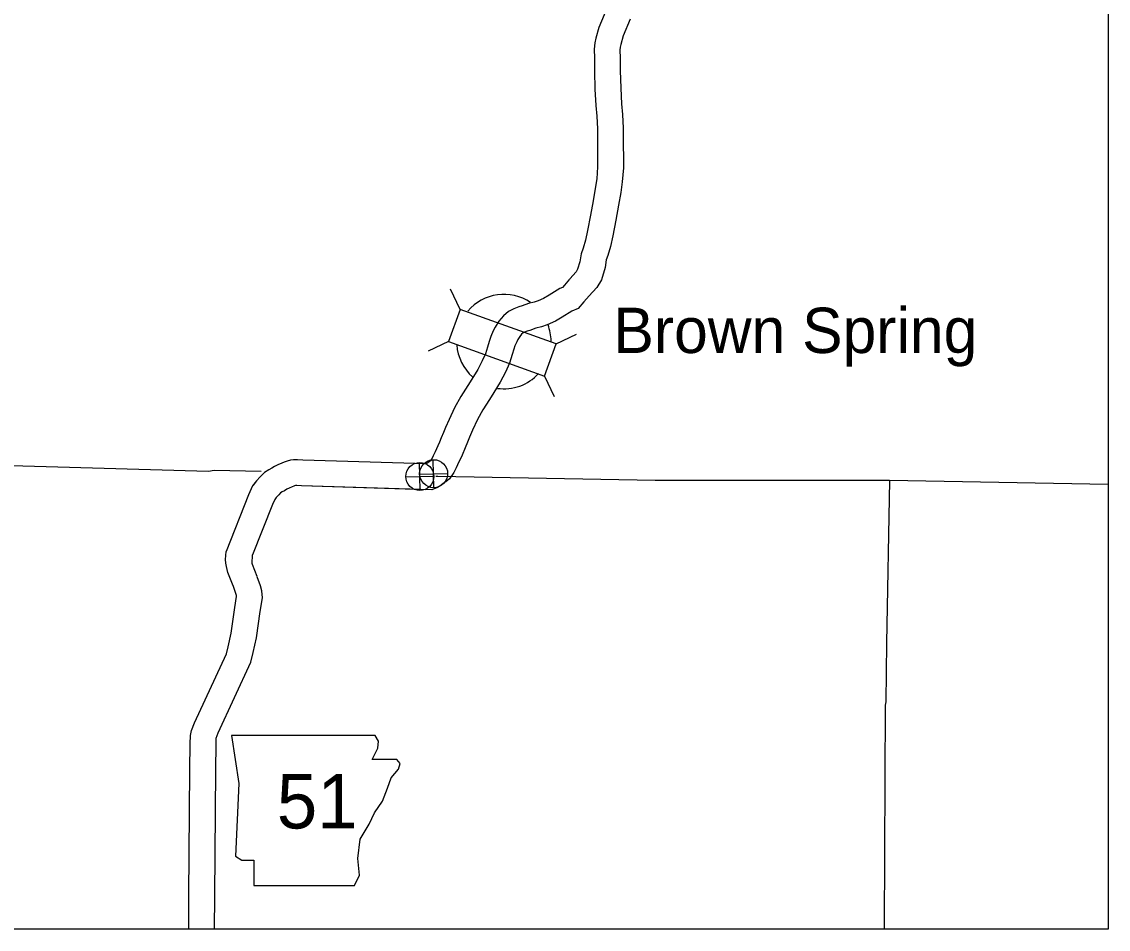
# Model space of a CAD drawing. Extents: x 1373862 to 1377080, y 1164775 to 1170415.
# Drawn here: x 1374487.3 to 1374613.9, y 1169861.9 to 1169967.7 of the extents above; entities that cross this region are included whole.
import ezdxf

# ---------------------------------------------------------------- set-up
doc = ezdxf.new("R2010")
doc.units = 0
doc.layers.add('1', color=7, linetype='Continuous')
doc.layers.add('Default', color=7, linetype='Continuous')

msp = doc.modelspace()

# ---------------------------------------------------------------- linework, layer by layer
at = {"layer": '1'}
msp.add_lwpolyline([(1373884.49, 1170388.77), (1374613.88, 1170388.77), (1374613.88, 1169861.94), (1373884.49, 1169861.94)], close=True, dxfattribs=at)
at = {"layer": 'Default'}
for p, q in [((1374538.38, 1169934.16), (1374537.26, 1169936.54)), ((1374549.56, 1169930.14), (1374551.95, 1169931.27)), ((1374537.04, 1169930.43), (1374534.66, 1169929.3)), ((1374548.23, 1169926.41), (1374549.35, 1169924.03)), ((1374533.74, 1169913.07), (1374533.66, 1169916.33)), ((1374535.35, 1169913.4), (1374535.27, 1169916.65)), ((1374532.07, 1169914.66), (1374535.33, 1169914.74)), ((1374533.68, 1169914.99), (1374536.94, 1169915.06))]:
    msp.add_line(p, q, dxfattribs=at)
for points in [[(1374555.47, 1169969.23), (1374554.56, 1169967.02), (1374554.21, 1169965.78), (1374554.09, 1169965.22), (1374554.01, 1169964.51), (1374554.03, 1169963.45), (1374554.04, 1169961.93), (1374554.1, 1169959.83), (1374554.19, 1169957.92), (1374554.3, 1169956.68), (1374554.38, 1169955.2), (1374554.4, 1169953.31), (1374554.41, 1169951.83), (1374554.41, 1169950.78), (1374554.3, 1169949.38), (1374554.14, 1169948.25), (1374553.9, 1169946.83), (1374553.59, 1169945.15), (1374553.23, 1169943.37), (1374552.98, 1169942.25), (1374552.71, 1169941.32), (1374552.49, 1169940.65), (1374552.34, 1169939.73), (1374552.08, 1169938.84), (1374551.89, 1169938.53), (1374551.17, 1169937.73)], [(1374558.21, 1169967.99), (1374557.4, 1169966.04), (1374557.12, 1169965.04), (1374557.05, 1169964.71), (1374557.01, 1169964.37), (1374557.03, 1169963.49), (1374557.04, 1169961.99), (1374557.1, 1169959.95), (1374557.18, 1169958.13), (1374557.3, 1169956.9), (1374557.38, 1169955.29), (1374557.4, 1169953.34), (1374557.41, 1169951.84), (1374557.41, 1169950.67), (1374557.28, 1169949.04), (1374557.1, 1169947.78), (1374556.85, 1169946.31), (1374556.54, 1169944.58), (1374556.17, 1169942.75), (1374555.89, 1169941.5), (1374555.58, 1169940.44), (1374555.42, 1169939.94), (1374555.27, 1169939.05), (1374554.84, 1169937.61), (1374554.3, 1169936.72), (1374553.39, 1169935.72)], [(1374551.14, 1169937.7), (1374550.54, 1169937.01), (1374550.31, 1169936.74), (1374550, 1169936.6), (1374548.75, 1169935.83), (1374548.12, 1169935.46), (1374547.47, 1169935.17), (1374547.01, 1169935.02), (1374546.34, 1169934.84), (1374545.61, 1169934.59), (1374545.23, 1169934.48), (1374544.63, 1169934.25), (1374544.03, 1169933.93), (1374543.43, 1169933.41), (1374542.9, 1169932.8), (1374542.48, 1169932.1), (1374542.26, 1169931.67), (1374541.98, 1169931.03), (1374541.77, 1169930.44), (1374541.59, 1169929.76), (1374541.33, 1169928.99), (1374540.97, 1169928.16), (1374540.45, 1169927.17), (1374539.76, 1169926.03), (1374539.3, 1169925.29), (1374538.48, 1169924.03), (1374537.73, 1169922.7), (1374537.1, 1169921.34), (1374536.7, 1169920.43), (1374536.47, 1169919.84), (1374536.2, 1169919.21), (1374535.99, 1169918.69), (1374535.79, 1169918.27), (1374535.47, 1169917.58), (1374535.45, 1169917.48), (1374535.42, 1169917.42), (1374535.24, 1169917.09), (1374535.04, 1169916.67), (1374534.93, 1169916.51), (1374534.73, 1169916.39), (1374534.43, 1169916.16), (1374520.09, 1169916.61), (1374519.45, 1169916.66), (1374519, 1169916.65), (1374518.64, 1169916.59), (1374518.26, 1169916.5), (1374517.9, 1169916.37), (1374517.63, 1169916.25), (1374517.16, 1169916.05), (1374516.79, 1169915.85), (1374516.47, 1169915.67), (1374516.12, 1169915.47), (1374515.61, 1169915.15), (1374515.12, 1169914.67), (1374514.69, 1169914.21), (1374514.31, 1169913.74)], [(1374553.42, 1169935.75), (1374552.81, 1169935.04), (1374552.15, 1169934.29), (1374551.42, 1169933.95), (1374550.29, 1169933.26), (1374549.5, 1169932.79), (1374548.54, 1169932.36), (1374547.87, 1169932.15), (1374547.22, 1169931.97), (1374546.5, 1169931.73), (1374546.2, 1169931.64), (1374545.89, 1169931.52), (1374545.73, 1169931.44), (1374545.55, 1169931.28), (1374545.34, 1169931.03), (1374545.11, 1169930.65), (1374544.98, 1169930.38), (1374544.76, 1169929.91), (1374544.63, 1169929.55), (1374544.46, 1169928.9), (1374544.14, 1169927.92), (1374543.68, 1169926.86), (1374543.06, 1169925.7), (1374542.32, 1169924.47), (1374541.83, 1169923.68), (1374541.05, 1169922.48), (1374540.4, 1169921.33), (1374539.83, 1169920.1), (1374539.47, 1169919.28), (1374539.25, 1169918.72), (1374538.97, 1169918.06), (1374538.62, 1169917.2), (1374538.1, 1169916.07), (1374537.92, 1169915.73), (1374537.65, 1169915.16), (1374537.14, 1169914.43), (1374536.71, 1169914.08), (1374536.44, 1169913.91), (1374536.13, 1169913.67), (1374535.74, 1169913.43), (1374535.09, 1169913.13), (1374519.93, 1169913.61), (1374519.36, 1169913.66), (1374519.28, 1169913.65), (1374519.22, 1169913.65), (1374519.12, 1169913.62), (1374519.03, 1169913.59), (1374518.83, 1169913.5), (1374518.47, 1169913.34), (1374518.22, 1169913.21), (1374517.93, 1169913.05), (1374517.67, 1169912.9), (1374517.49, 1169912.79), (1374517.27, 1169912.58), (1374516.96, 1169912.24), (1374516.8, 1169912.04)], [(1374515.21, 1169915.27), (1374509.73, 1169915.41), (1374509.09, 1169915.29), (1374483.39, 1169916.02), (1374482.97, 1169916.02), (1374456.39, 1169916.83), (1374430.79, 1169917.15), (1374430.16, 1169917.09)], [(1374534.43, 1169916.16), (1374520.09, 1169916.61), (1374519.45, 1169916.66), (1374519, 1169916.65), (1374518.64, 1169916.59), (1374518.26, 1169916.5), (1374517.9, 1169916.37), (1374517.63, 1169916.25), (1374517.16, 1169916.05), (1374516.79, 1169915.85), (1374516.47, 1169915.67), (1374516.12, 1169915.47), (1374515.61, 1169915.15), (1374515.12, 1169914.67), (1374514.69, 1169914.21), (1374514.21, 1169913.61), (1374513.75, 1169912.56), (1374511.15, 1169905.95)], [(1374613.88, 1169913.76), (1374588.41, 1169914.23), (1374561.82, 1169914.23), (1374561.1, 1169914.25), (1374535.78, 1169914.69), (1374535.57, 1169914.72)], [(1374534.38, 1169913.16), (1374519.93, 1169913.61), (1374519.36, 1169913.66), (1374519.28, 1169913.65), (1374519.22, 1169913.65), (1374519.12, 1169913.62), (1374519.03, 1169913.59), (1374518.83, 1169913.5), (1374518.47, 1169913.34), (1374518.22, 1169913.21), (1374517.93, 1169913.05), (1374517.67, 1169912.9), (1374517.49, 1169912.79), (1374517.27, 1169912.58), (1374516.96, 1169912.24), (1374516.8, 1169912.04), (1374516.53, 1169911.42), (1374514.23, 1169905.59)], [(1374588.41, 1169914.23), (1374588.06, 1169895.3)], [(1374588.41, 1169914.23), (1374588.06, 1169895.3)], [(1374511.96, 1169901.95), (1374511.34, 1169903.52), (1374511.17, 1169904.21), (1374511.11, 1169904.61), (1374511.08, 1169905.03), (1374511.15, 1169905.95)], [(1374514.75, 1169903.04), (1374514.21, 1169904.43), (1374514.18, 1169904.55), (1374514.23, 1169905.59)], [(1374506.79, 1169861.94), (1374506.81, 1169865.84), (1374506.93, 1169880.55), (1374506.97, 1169883.55), (1374506.98, 1169884.53), (1374507.11, 1169885.09), (1374507.47, 1169886), (1374511.17, 1169894.05), (1374511.37, 1169894.87), (1374511.71, 1169896.45), (1374512.15, 1169899.42), (1374512.34, 1169900.71), (1374512.33, 1169900.85), (1374512.27, 1169901.07), (1374511.94, 1169901.99)], [(1374509.79, 1169861.94), (1374509.81, 1169865.82), (1374509.93, 1169880.52), (1374509.97, 1169883.5), (1374509.98, 1169884.18), (1374509.98, 1169884.2), (1374510.23, 1169884.82), (1374514.01, 1169893.05), (1374514.3, 1169894.19), (1374514.67, 1169895.92), (1374515.11, 1169898.98), (1374515.36, 1169900.58), (1374515.3, 1169901.36), (1374515.14, 1169901.97), (1374514.77, 1169903)], [(1374588.06, 1169895.3), (1374587.96, 1169888.44), (1374587.89, 1169888.05), (1374587.77, 1169862.2), (1374587.77, 1169861.94)]]:
    msp.add_lwpolyline(points, dxfattribs=at)
for points in [[(1374537.04, 1169930.43), (1374548.23, 1169926.41), (1374549.56, 1169930.14), (1374538.38, 1169934.16)], [(1374511.77, 1169884.52), (1374512.61, 1169878.94), (1374512.24, 1169870.47), (1374512.98, 1169870.01), (1374514.38, 1169870.01), (1374514.38, 1169867.03), (1374526.1, 1169867.03), (1374526.66, 1169868.24), (1374526.47, 1169870.19), (1374526.75, 1169872.43), (1374527.78, 1169874.19), (1374528.43, 1169875.5), (1374529.36, 1169876.89), (1374529.92, 1169878.38), (1374530.38, 1169879.59), (1374531.22, 1169880.61), (1374531.4, 1169881.26), (1374531.03, 1169881.73), (1374528.15, 1169881.73), (1374528.8, 1169883.03), (1374528.89, 1169883.87), (1374528.51, 1169884.51)]]:
    msp.add_lwpolyline(points, close=True, dxfattribs=at)
for centre in [(1374533.7, 1169914.7), (1374535.31, 1169915.03)]:
    msp.add_circle(centre, 1.63, dxfattribs=at)
for start, end in [(55.571, 140.0308), (0.6969, 20.8357), (183.8141, 228.5639), (262.0275, 317.3941)]:
    msp.add_arc((1374543.49, 1169930.42), 5.5, start, end, dxfattribs=at)

# ---------------------------------------------------------------- texts
for s, height, p in [('Brown Spring', 5.28, (1374556.25, 1169929.09)), ('51', 6.336, (1374517.04, 1169873.69))]:
    msp.add_text(s, height=height, dxfattribs=at).set_placement(p)

doc.saveas('drawing.dxf')
